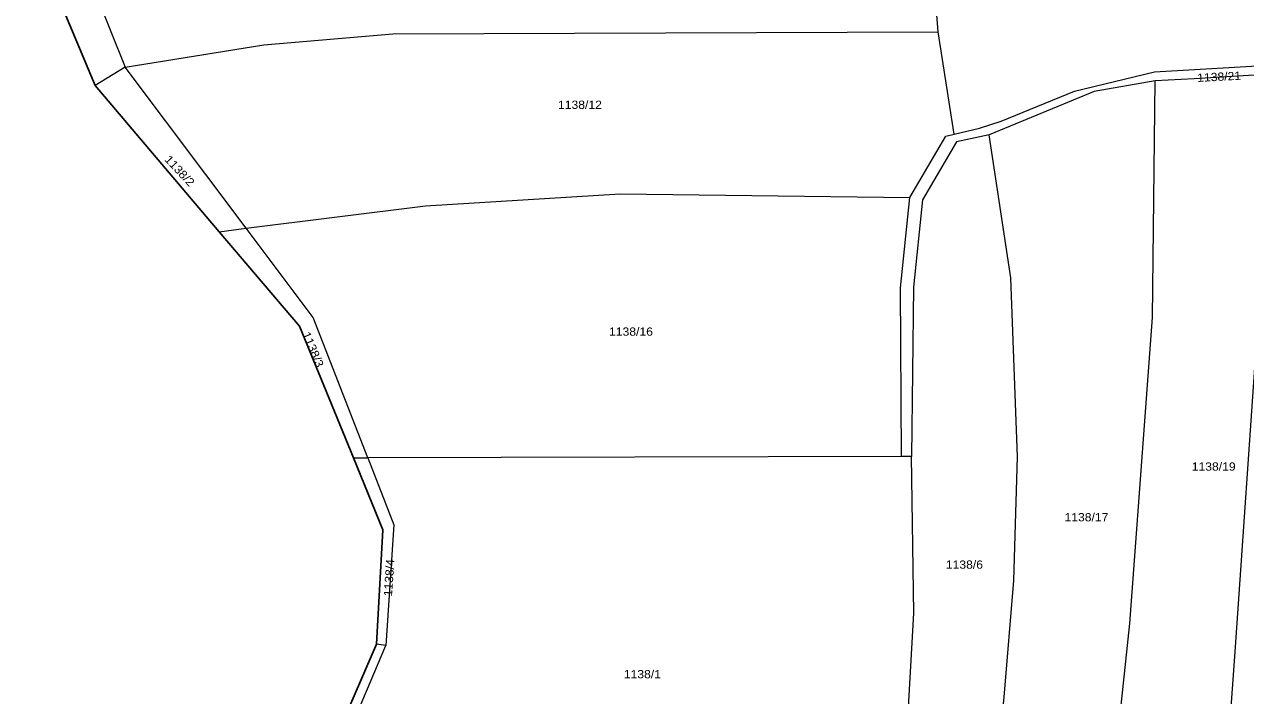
# Model space of a CAD drawing. Extents: x -686207 to -681951, y -1020493 to -1017811.
# Drawn here: x -684572.6 to -684321.3, y -1019462.2 to -1019323.9 of the extents above; entities that cross this region are included whole.
import ezdxf

# ---------------------------------------------------------------- set-up
doc = ezdxf.new("R2010")
doc.units = 0
doc.header["$LTSCALE"] = 0.4
doc.layers.add('1', color=7, linetype='Continuous', lineweight=13)
doc.layers.add('24', color=7, linetype='Continuous', lineweight=25)
doc.layers.add('2', color=7, linetype='Continuous')

msp = doc.modelspace()

# ---------------------------------------------------------------- linework, layer by layer
at = {"layer": '1'}
for p, q in [((-684558.08, -1019336.52), (-684572.61, -1019301.76)), ((-684564.87, -1019300.16), (-684551.9, -1019332.74)), ((-684551.9, -1019332.74), (-684558.08, -1019336.52)), ((-684526.97, -1019365.93), (-684551.9, -1019332.74)), ((-684532.51, -1019366.63), (-684558.08, -1019336.52)), ((-684532.51, -1019366.63), (-684526.97, -1019365.93)), ((-684392.15, -1019412.9), (-684501.95, -1019413.2)), ((-684390.06, -1019412.95), (-684392.15, -1019412.9)), ((-684504.89, -1019413.21), (-684501.95, -1019413.2)), ((-684512.05, -1019478.99), (-684500.14, -1019451.56))]:
    msp.add_line(p, q, dxfattribs=at)
for points in [[(-684384.55, -1019325.45), (-684386.92, -1019295.82), (-684267.9, -1019301.39)], [(-684551.9, -1019332.74), (-684523.32, -1019328.15), (-684496.77, -1019325.89), (-684384.55, -1019325.45)], [(-684390.43, -1019359.56), (-684382.98, -1019346.97), (-684381.27, -1019346.56), (-684384.55, -1019325.45)], [(-684381.27, -1019346.56), (-684376.08, -1019345.32), (-684371.61, -1019343.88), (-684356.52, -1019337.72), (-684340.04, -1019333.72), (-684314.17, -1019332.17), (-684268.3, -1019330.88)], [(-684316.37, -1019334.22), (-684318.43, -1019334.36), (-684331.87, -1019335.14), (-684339.89, -1019335.57)], [(-684316.37, -1019334.22), (-684318.95, -1019386.68), (-684323.56, -1019453.16), (-684326.18, -1019490.28), (-684301.22, -1019485.17)], [(-684339.89, -1019335.57), (-684352.47, -1019337.74), (-684374.08, -1019346.69)], [(-684350.13, -1019494.54), (-684345.11, -1019447.28), (-684340.49, -1019384.31), (-684339.89, -1019335.57)], [(-684374.08, -1019346.69), (-684380.83, -1019348.15), (-684387.83, -1019360.06), (-684389.68, -1019378.08), (-684390.06, -1019412.95)], [(-684373.1, -1019482.84), (-684370.99, -1019462.51), (-684368.99, -1019438.47), (-684368.22, -1019412.97), (-684369.6, -1019376.14), (-684374.08, -1019346.69)], [(-684526.97, -1019365.93), (-684490.07, -1019361.27), (-684450.03, -1019358.8), (-684390.43, -1019359.56)], [(-684392.15, -1019412.9), (-684392.34, -1019378.16), (-684390.43, -1019359.56)], [(-684504.89, -1019413.21), (-684516.02, -1019386.05), (-684532.51, -1019366.63)], [(-684501.95, -1019413.2), (-684513.18, -1019384.29), (-684526.97, -1019365.93)], [(-684500.14, -1019451.56), (-684498.83, -1019427.99), (-684504.89, -1019413.21)], [(-684501.95, -1019413.2), (-684496.6, -1019426.96), (-684498.25, -1019451.87), (-684500.14, -1019451.56)], [(-684393.4, -1019484.79), (-684390.98, -1019469.4), (-684389.59, -1019445.21), (-684390.06, -1019412.95)], [(-684513.25, -1019487.11), (-684510.18, -1019480.08), (-684498.25, -1019451.87)]]:
    msp.add_lwpolyline(points, dxfattribs=at)
at = {"layer": '24'}
msp.add_lwpolyline([(-684572.61, -1019301.76), (-684558.08, -1019336.52), (-684532.51, -1019366.63), (-684516.02, -1019386.05), (-684504.89, -1019413.21), (-684498.83, -1019427.99), (-684500.14, -1019451.56), (-684512.05, -1019478.99)], dxfattribs=at)

# ---------------------------------------------------------------- texts
at = {"layer": '2', "width": 1.1}
for s, rotation, p in [('1138/21', 3, (-684331.225, -1019335.798)), ('1138/2', 313, (-684543.891, -1019351.869)), ('1138/3', 293, (-684515.492, -1019387.692)), ('1138/4', 86, (-684496.982, -1019441.759))]:
    msp.add_text(s, height=1.7, rotation=rotation, dxfattribs=at).set_placement(p)
for s, p in [('1138/12', (-684462.81, -1019341.34)), ('1138/16', (-684452.31, -1019388.049)), ('1138/19', (-684332.4, -1019415.84)), ('1138/17', (-684358.58, -1019426.27)), ('1138/6', (-684383, -1019436.03)), ('1138/1', (-684449.27, -1019458.6))]:
    msp.add_text(s, height=1.7, dxfattribs=at).set_placement(p)

doc.saveas('drawing.dxf')
